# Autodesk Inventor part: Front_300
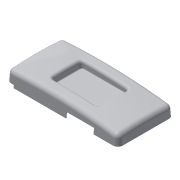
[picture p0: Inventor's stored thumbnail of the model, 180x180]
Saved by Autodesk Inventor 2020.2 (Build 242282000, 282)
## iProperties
Created: 2006-05
Part Number: Front_300
Document SubType Name: Modeling
Designer: F.Stasiak
Density: 1 g/cm^3
Material: Ogólny
Appearance: Biały
Manager: www.cadconsulting.pl
Company: Fabian Stasiak CAD Consulting
Author: F.Stasiak
Subject: Zbiór ćwiczeń. Autodesk Inventor 2020. Kurs podstawowy
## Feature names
1. Extrusion1
2. Fillet3
3. Split1
4. Wyciągnięcie proste7 [Extrusion]
5. Zaokrąglenie10 [Fillet]
6. Zaokrąglenie11 [Fillet]
7. Fillet4
8. Zaokrąglenie12 [Fillet]
9. Shell1
10. Extrusion3
11. Wyciągnięcie proste4 [Extrusion]
12. Wyciągnięcie proste5 [Extrusion]
## Parameters: d3 = -3 deg, d12 = 5 mm, d13 = 0, d14 = 5 mm, d16 = 1 mm, d17 = 4 mm, d18 = 1 mm, d19 = 1 mm, d20 = 1 deg, d27 = 49 mm, d28 = 49 mm, d29 = 6 mm, d31 = 2 deg, d32 = 0, d34 = 4 mm, d36 = 52 mm, d37 = 6 mm, d38 = 3 mm, d40 = 0, d42 = 0, d51 = 9.25 mm, d53 = 32 mm, d54 = 6 mm, d55 = 2.5 deg, d56 = 3 mm, d57 = 1 mm, d58 = 3 mm
